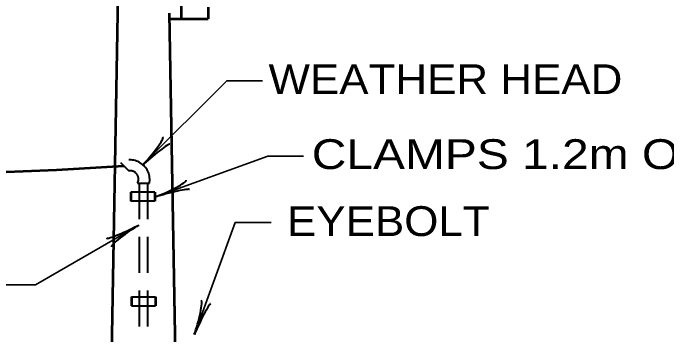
# Model space of a CAD drawing. Extents: x 14808 to 15663, y 10944 to 11488.
# Drawn here: x 14944.7 to 15010.4, y 11406.8 to 11439.2 of the extents above; entities that cross this region are included whole.
import ezdxf

# ---------------------------------------------------------------- set-up
doc = ezdxf.new("R2010")
doc.units = 0
doc.header["$LTSCALE"] = 1.2
doc.linetypes.add('MEDIUM_DASHED', pattern=[4.5, 3, -1.5])
doc.layers.add('1', color=7, linetype='Continuous', lineweight=53)

msp = doc.modelspace()

# ---------------------------------------------------------------- linework, layer by layer
at = {"layer": '1'}
for p, q in [((14955.422, 11450.597), (14953.012, 11312.559)), ((14955.422, 11450.597), (14953.013, 11312.598)), ((14955.422, 11450.597), (14953.013, 11312.565)), ((14961.632, 11442.227), (14961.632, 11438.627)), ((14964.332, 11439.827), (14964.332, 11438.627)), ((14960.421, 11439.219), (14960.421, 11439.185)), ((14960.421, 11439.186), (14963.321, 11273.024)), ((14960.421, 11439.185), (14963.259, 11276.623)), ((14960.421, 11439.185), (14963.259, 11276.623)), ((14960.431, 11438.627), (14961.632, 11438.627)), ((14961.632, 11438.627), (14964.332, 11438.627))]:
    msp.add_line(p, q, dxfattribs=at)
at = {"layer": '1', "linetype": 'MEDIUM_DASHED', "lineweight": 40}
for p, q in [((14955.508, 11424.2), (14956.356, 11423.351)), ((14957.222, 11422.097), (14958.422, 11422.097)), ((14957.402, 11422.097), (14957.402, 11404.097)), ((14958.242, 11422.097), (14958.242, 11404.097)), ((14958.958, 11421.197), (14956.558, 11421.197)), ((14958.958, 11420.297), (14956.558, 11420.297)), ((14956.622, 11410.684), (14959.022, 11410.684)), ((14956.622, 11409.784), (14959.022, 11409.784))]:
    msp.add_line(p, q, dxfattribs=at)
at = {"layer": '1', "linetype": 'MEDIUM_DASHED'}
for p, q in [((14956.558, 11421.197), (14956.558, 11420.297)), ((14958.958, 11421.197), (14958.958, 11420.297)), ((14956.622, 11410.684), (14956.622, 11409.784)), ((14959.022, 11410.684), (14959.022, 11409.784))]:
    msp.add_line(p, q, dxfattribs=at)
at = {"layer": '1', "lineweight": 35}
for points in [[(14957.71, 11423.92), (14966.196, 11432.406), (14969.796, 11432.406)], [(14959.041, 11420.727), (14970.317, 11424.832), (14973.917, 11424.832)], [(14962.943, 11406.891), (14967.047, 11418.168), (14970.647, 11418.168)], [(14957.356, 11417.889), (14946.963, 11411.889), (14943.363, 11411.889)]]:
    msp.add_lwpolyline(points, dxfattribs=at)
at = {"layer": '1'}
msp.add_arc((14928.846, 11821.897), 398.946, 266.11935, 273.88065, dxfattribs=at)
at = {"layer": '1', "linetype": 'MEDIUM_DASHED', "lineweight": 40}
for centre, radius, start, end in [((14956.468, 11422.459), 1.988, 349.50124, 118.8707), ((14956.48, 11422.511), 0.85, 330.86779, 98.35179)]:
    msp.add_arc(centre, radius, start, end, dxfattribs=at)
at = {"layer": '1', "lineweight": 40}
for centre, major_axis, ratio, start_param, end_param in [((14958.402, 11425.081), (-1.383, -1.648), 0.122415, 0.896353, 3.141593), ((14958.841, 11424.691), (1.639, 1.341), 0.07063, 6.282307, 8.559703), ((14960.158, 11421.487), (-1.95, -0.909), 0.122415, 0.896353, 3.141593), ((14960.391, 11420.949), (2.053, 0.523), 0.07063, 6.282307, 8.559703), ((14956.064, 11417.437), (-1.931, -0.871), 0.07063, 6.282307, 8.559703), ((14956.387, 11416.947), (1.762, 1.234), 0.122415, 0.896353, 3.141593), ((14963.079, 11408.235), (-0.557, -2.078), 0.122415, 0.896353, 3.141593), ((14963.642, 11408.068), (0.919, 1.909), 0.07063, 6.282307, 8.559703)]:
    msp.add_ellipse(centre, major_axis=major_axis, ratio=ratio, start_param=start_param, end_param=end_param, dxfattribs=at)

# ---------------------------------------------------------------- texts
at = {"layer": '1'}
for s, width, p in [('WEATHER HEAD', 1.1, (14970.393, 11431.068)), ('CLAMPS 1.2m ON CENTER', 1.2, (14974.739, 11423.529)), ('EYEBOLT', 1.1, (14972.256, 11416.789))]:
    msp.add_text(s, height=3, dxfattribs=dict(at, width=width)).set_placement(p)

doc.saveas('drawing.dxf')
